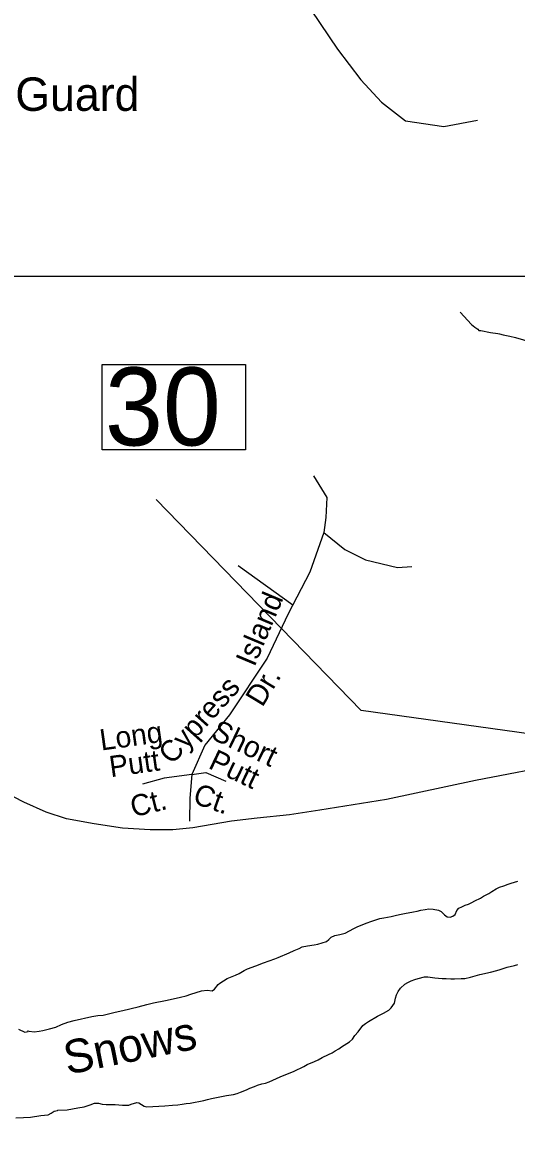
# Model space of a CAD drawing. Extents: x 2290055 to 2389491, y 66597 to 237875.
# Drawn here: x 2329443 to 2331660, y 111445 to 116521 of the extents above; entities that cross this region are included whole.
import ezdxf

# ---------------------------------------------------------------- set-up
doc = ezdxf.new("R2010")
doc.units = 0
for name, color, linetype in [('Exist Aviation Coast Guard Station Label', 7, 'Continuous'), ('Exist Hydrographic Island Shore', 7, 'Continuous'), ('Exist Hydrographic Point Label', 7, 'Continuous'), ('Exist Road Non-System Type 51', 7, 'Continuous'), ('Exist Road Non-System Type 51 Label', 7, 'Continuous'), ('Exist Road Primary US Structure Standard Bridge Number Label', 7, 'Continuous'), ('Exist Road Secondary Type 51 Attributed', 7, 'Continuous'), ('Map Preparation Inset Cut Line', 7, 'Continuous')]:
    doc.layers.add(name, color=color, linetype=linetype)

msp = doc.modelspace()

# ---------------------------------------------------------------- linework, layer by layer
at = {"layer": 'Exist Hydrographic Island Shore'}
for points in [[(2331214, 112531.8), (2331231, 112535.8), (2331250, 112539.6), (2331267.2, 112541.9), (2331285.5, 112541), (2331309.2, 112536.9), (2331321.2, 112530.5), (2331336.7, 112515.9), (2331349.5, 112506.9), (2331362, 112505.5), (2331374, 112509.3), (2331385, 112517.4), (2331392.7, 112534.5), (2331401.7, 112546), (2331414.5, 112552.1), (2331429.2, 112558.4), (2331444.5, 112563.8), (2331459.5, 112571.2), (2331472.7, 112578.2), (2331498.5, 112590.8), (2331512.2, 112598.8), (2331535.5, 112611.3), (2331550, 112619.7), (2331569.5, 112631.7), (2331584.5, 112639.9), (2331603, 112646.3), (2331622.5, 112653.7), (2331636.7, 112658.3), (2331665.5, 112666.8)], [(2329424.7, 112002.2), (2329452, 111988.4), (2329467, 111991.6), (2329466.7, 111995.1), (2329472.7, 111993.5), (2329495, 111990.8), (2329517, 111993), (2329533.7, 111995.9), (2329564, 112003.1), (2329591, 112012), (2329617, 112023.5), (2329645, 112033.4), (2329673.7, 112040.7), (2329754, 112059.2), (2329780.7, 112064.1), (2329804, 112065.5), (2329858.5, 112078.1), (2329892, 112086.8), (2329961, 112101.9), (2330000, 112112.8), (2330030, 112120.1), (2330083.7, 112131), (2330132.7, 112141.7), (2330151.2, 112146.3), (2330177.2, 112152.2), (2330198, 112159.2), (2330246.5, 112174.3), (2330270.7, 112177.4), (2330293.2, 112174.5), (2330304.2, 112182), (2330320.2, 112203.2), (2330328, 112208.4), (2330361.2, 112229.4), (2330383, 112239.4), (2330398, 112244.2), (2330415, 112252.1), (2330437.5, 112265.2), (2330452.7, 112272.6), (2330490, 112286), (2330524.7, 112299.5), (2330574.7, 112317.6), (2330590.2, 112323.8), (2330639.2, 112344.2), (2330662.2, 112355.6), (2330684.5, 112364.9), (2330698.2, 112371.2), (2330721.2, 112376.7), (2330751, 112380.2), (2330768, 112383.3), (2330787.7, 112389.1), (2330807.2, 112396.2), (2330817.2, 112404.3), (2330828.7, 112414.8), (2330844, 112422.6), (2330866.7, 112427.3), (2330890.5, 112433.9), (2330929.7, 112454.6), (2330944, 112461.7), (2330985.2, 112478.4), (2331010.2, 112487.2), (2331046.7, 112498.9), (2331065.2, 112502.6), (2331097.5, 112508.2), (2331114.7, 112512.1), (2331134.5, 112517.1), (2331157.5, 112522), (2331197.5, 112528.4), (2331214, 112531.8)], [(2329799.2, 111666), (2329817.7, 111664), (2329840.7, 111664.7), (2329858.7, 111664.3), (2329874.5, 111661.9), (2329890.7, 111661.1), (2329919.5, 111661.6), (2329930, 111666.1), (2329954.7, 111672.8), (2329964.7, 111671.8), (2329987.7, 111656.3), (2330000, 111654), (2330081, 111657.4), (2330116, 111661.2), (2330139.7, 111662.8), (2330159.5, 111665.9), (2330177.5, 111668.3), (2330195, 111670.1), (2330256, 111682.4), (2330273, 111686), (2330290.2, 111690.3), (2330358, 111704.2), (2330389.2, 111709), (2330405.7, 111713.7), (2330420.5, 111719.3), (2330448.5, 111730.6), (2330462.2, 111737.9), (2330483.5, 111745.3), (2330497.5, 111750.9), (2330517.2, 111757.5), (2330533, 111760.6), (2330549, 111766.3), (2330598.5, 111787.7), (2330662.5, 111813.6), (2330705.5, 111834.9), (2330720.5, 111843), (2330752.5, 111856.8), (2330769.2, 111864.9), (2330787.7, 111874.9), (2330816.5, 111888.6), (2330832, 111896.6), (2330846, 111904.7), (2330861.7, 111914.4), (2330875, 111923.3), (2330910, 111944.9), (2330924, 111957.9), (2330935, 111973.8), (2330948.5, 111990.4), (2330970, 112018.2), (2330982.7, 112028.3), (2330996, 112036.7), (2331035.5, 112060.5), (2331063.2, 112074.8), (2331087.5, 112086.9), (2331098, 112097.9), (2331113, 112119.5), (2331117, 112141.9), (2331122, 112156.8), (2331129.2, 112171.8), (2331139.2, 112186.4), (2331158.7, 112203.6), (2331172, 112211.6), (2331187.5, 112218.6), (2331203, 112224.9), (2331218.5, 112229.7), (2331246.7, 112236.7), (2331262.7, 112237.3), (2331293, 112233.3), (2331310, 112231.8), (2331326.2, 112230.3), (2331345, 112229.1), (2331365.2, 112228.5), (2331381.5, 112228.3), (2331412, 112229), (2331428.5, 112230.3), (2331453.5, 112235.7), (2331495.5, 112247), (2331543, 112258.2), (2331572.5, 112265.8), (2331586.7, 112270.5), (2331617.7, 112279.9), (2331650.7, 112287.7), (2331666.2, 112292.9)], [(2329411.7, 111604.7), (2329446.5, 111605.1), (2329477.5, 111607), (2329525, 111614.1), (2329558, 111617.6), (2329571.2, 111625), (2329583.7, 111634.5), (2329599.5, 111636.9), (2329600.7, 111639), (2329642.7, 111639.9), (2329690, 111649.5), (2329719.5, 111653.8), (2329746.5, 111661.9), (2329765, 111670.7), (2329783.7, 111670), (2329799.2, 111666)]]:
    msp.add_lwpolyline(points, dxfattribs=at)
at = {"layer": 'Exist Road Non-System Type 51'}
for points in [[(2329773.9, 118006.1), (2330856.5, 116401.6), (2330961.2, 116263.3), (2331053.3, 116162.8), (2331162.2, 116079), (2331333.8, 116053.9), (2331484.5, 116083.2)], [(2331407.1, 115221), (2331457.5, 115165.5), (2331473.7, 115153.7), (2331485.9, 115144), (2331491.7, 115138), (2331499.9, 115138), (2331543.9, 115130.2), (2331575.9, 115124.9), (2331583.1, 115123.2)], [(2331583.1, 115123.2), (2331600.1, 115119), (2331630.2, 115113.3), (2331656.4, 115107.7), (2331692.3, 115096), (2331726.5, 115086.2), (2331744.8, 115080.4), (2331758.6, 115078.6), (2331770.5, 115076.8), (2331788.5, 115079.2), (2331808.6, 115077.3), (2331886.6, 115088), (2332018.5, 115105.3), (2332166.3, 115126.9), (2332216.2, 115135.4), (2332282.1, 115138), (2332360, 115142.7), (2332490, 115142.3), (2332694.1, 115142.5), (2332984.1, 115139.5), (2333188.5, 115138.7)], [(2330749, 114486.3), (2330808.3, 114388.7), (2330804.1, 114299.6), (2330795.6, 114231.7), (2330732, 114053.5), (2330634.5, 113866.7), (2330541.2, 113667.2), (2330371.5, 113412.6), (2330261.3, 113276.8), (2330201.9, 113145.2), (2330265.5, 113153.7), (2330354.6, 113115.5)], [(2330795.6, 114231.7), (2330888.9, 114155.3), (2330982.2, 114108.6), (2331126.4, 114074.7), (2331190, 114078.9)], [(2330409.7, 114083.2), (2330655.7, 113907.3)], [(2330201.9, 113145.2), (2330078.9, 113128.3), (2329981.3, 113102.8)], [(2330201.9, 113145.2), (2330193.4, 113039.1), (2330192.6, 112936)]]:
    msp.add_lwpolyline(points, dxfattribs=at)
at = {"layer": 'Exist Road Primary US Structure Standard Bridge Number Label'}
msp.add_lwpolyline([(2329799.7, 114985.2), (2330443.8, 114985.2), (2330443.8, 114602.8), (2329799.7, 114602.8)], close=True, dxfattribs=at)
msp.add_lwpolyline([(2333069.9, 113139.8), (2330962.2, 113433.3), (2330041.7, 114380.5)], dxfattribs=at)
at = {"layer": 'Exist Road Secondary Type 51 Attributed'}
msp.add_lwpolyline([(2332286.8, 113273.9), (2331476.7, 113118.6), (2331075.9, 113033.9), (2330776.7, 112985.9), (2330640.9, 112964.1), (2330495.5, 112948.9), (2330380.3, 112935.5), (2330206.5, 112906.5), (2330117.5, 112897.7), (2330014.6, 112897.7), (2329890.7, 112904.7), (2329763.4, 112923.9), (2329639.5, 112946.6), (2329548.8, 112976.3), (2329447.6, 113021.7), (2329358.6, 113067)], dxfattribs=at)
at = {"layer": 'Map Preparation Inset Cut Line'}
for points in [[(2318953.4, 149726.2), (2325417.5, 149726.2), (2346393.7, 149726.2), (2338303.7, 115381.1), (2324894.8, 115381.1)], [(2327293.1, 115381.1), (2326421, 108601.1), (2323940.9, 84753.9), (2319662, 79548.4), (2319961.8, 76608.6), (2326693.5, 76608.6), (2329528, 82750.7), (2336452.5, 105360.7), (2339748.2, 115381.1)]]:
    msp.add_lwpolyline(points, close=True, dxfattribs=at)

# ---------------------------------------------------------------- texts
at = {"layer": 'Exist Aviation Coast Guard Station Label'}
msp.add_text('U.S. Coast Guard', height=150, dxfattribs=at).set_placement((2328384.1, 116124.5))
at = {"layer": 'Exist Hydrographic Point Label'}
msp.add_text('Snows', height=150, rotation=11.3794, dxfattribs=at).set_placement((2329643.5, 111797.6))
at = {"layer": 'Exist Road Non-System Type 51 Label'}
for s, rotation, p in [(' Island ', 67.1787, (2330470, 113592.6)), ('Cypress', 48.1744, (2330114.1, 113185.8)), ('Dr.', 58.8391, (2330519.2, 113444.1)), ('Long', 7.9521, (2329795.6, 113252.7)), ('Short', 334.4808, (2330283, 113308.7)), ('Putt', 7.9521, (2329838.4, 113133)), ('Putt', 334.4808, (2330271.8, 113176)), ('Ct.', 340.6434, (2330201.5, 113018.9)), ('Ct.', 13.7445, (2329939.5, 112952.8))]:
    msp.add_text(s, height=95, rotation=rotation, dxfattribs=at).set_placement(p)
at = {"layer": 'Exist Road Primary US Structure Standard Bridge Number Label'}
msp.add_text('30', height=350, dxfattribs=at).set_placement((2329812.2, 114622.6))

doc.saveas('drawing.dxf')
